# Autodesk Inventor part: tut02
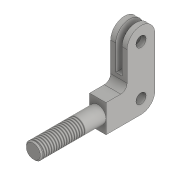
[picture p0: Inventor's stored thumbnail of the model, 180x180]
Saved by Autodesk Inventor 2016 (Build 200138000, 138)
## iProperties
Created: 2015-03
Part Number: tut02
Material: Generic
Document SubType Name: Modeling
Designer: Sandeep
Density: 1 g/cm^3
Appearance: Default
Author: Sandeep
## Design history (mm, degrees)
sketch "Sketch1"
  geometry: L1 (0, 0)-(0, 22); L2 (0, 22)-(11.652, 22); L3 (16.652, 27)-(16.652, 50); L4 (38.652, 50)-(38.652, 11); L5 (27.652, 0)-(0, 0); A1 r 11 centre (27.652, 50) between (38.652, 50) and (16.652, 50); A2 r 11 centre (27.652, 11) between (27.652, 0) and (38.652, 11); A3 r 5 centre (11.652, 27) between (11.652, 22) and (16.652, 27)
  constraints: 10 end point, 6 point on circle, 6 tangent, 3 centre point, 3 perpendicular, 1 parallel, 1 vertical
  dimensions: "d0" = 11 radius of A1; "d1" = 11 radius of A2; "d2" = 5 radius of A3; "d3" = 38.65217 distance between parallel lines of L1 L4; "d4" = 22 distance between parallel lines of L5 L2; "d5" = 50 distance from line of A1.centre L5
extrude "Extrusion1" new body sketch "Sketch1" stored distance "d6" = 13; taper "d7" = 0 deg
hole "Hole1" diameter "d10" = 8; stored, may be unused: countersink angle "d14" = 90 deg, drill point angle "d16" = 118 deg; dims "d8" = 10, "d9" = 10, "d11" = 6, "d12" = 4, "d13" = 2, "d15" = 8
hole "Hole2" diameter "d19" = 8; stored, may be unused: countersink angle "d23" = 90 deg, drill point angle "d25" = 118 deg; dims "d17" = 10, "d18" = 10, "d20" = 6, "d21" = 4, "d22" = 2, "d24" = 8
sketch "Sketch2"
  geometry: L1 (0, -11)-(13, -11) reference; L2 (4, -11)-(4, 20); L3 (4, 20)-(9, 20); L4 (9, 20)-(9, -11); L5 (6.5, 50)-(6.5, -21.602); L6 (13, 50)-(0, 50) reference; L7 (9, -11)-(4, -11)
  constraints: 10 end point, 2 perpendicular, 2 point on line, 2 vertical, 1 collinear, 1 other
  dimensions: "d26" = 5 distance between parallel lines of L4 L2; "d27" = 30 distance between parallel lines of L6 L3
extrude "Extrusion2" cut sketch "Sketch2" stored distance "d28" = 13; taper "d29" = 0 deg
sketch "Sketch3"
  geometry: L1 (13, 0)-(0, 0) reference; L2 (6.5, 0)-(6.5, 35.061); C1 r 6.5 at (6.5, 11)
  constraints: 2 end point, 1 centre point, 1 point on line, 1 vertical
  dimensions: "d30" = 13 diameter of C1; "d31" = 11 distance from line of C1.centre L1
extrude "Extrusion3" join sketch "Sketch3" distance "d32" = 51; taper "d33" = 0 deg
chamfer "Chamfer1" distance "d34" = 1; stored, may be unused: second distance "d35" = 2, angle "d36" = 45 deg
thread "Thread1" dims "d37" = 34, "d38" = 0
body "Solid1"
